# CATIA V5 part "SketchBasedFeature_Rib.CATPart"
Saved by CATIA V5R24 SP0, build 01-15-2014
Part number: Part1
Bounding box of the stored display mesh (mm): x -138.345 to 158.897, y -708.244 to 25, z -53.996 to 200
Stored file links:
  E:\Desktop_RNH\학부 CAD 수업 자료\[CAD_V2]강의자료(CAD)_2017년 이후\툴바예제\2 PartDesign\Upload2_1_modified\SketchBasedFeature_Rib.CATPart

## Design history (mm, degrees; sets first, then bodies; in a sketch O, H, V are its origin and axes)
Set1
  Plane1: type Offset, RefPlane zx-plane, Offset 25
  Plane2: type Offset, RefPlane zx-plane, Offset 25, reversed
  Sketch1 on Plane1, origin (0, 25, 0), H (-1, 0, 0), V (0, 0, 1)
    line L1 (0, 0) -> (30, 0)
    arc A1 centre (30, -70) radius 70 from (30, 0) to (79.8659, -20.8737) cw
    line L2 (79.8659, -20.8737) -> (112.4973, -53.9964)
    horizontal: L1 H
    tangency: A1 L1, A1 L2
  Sketch2 on Plane2, origin (0, -25, 0), H (-1, 0, 0), V (0, 0, 1)
    line L1 (0, 0) -> (91.7373, 0)
    arc A1 centre (91.7373, -25.9663) radius 25.9663 from (91.7373, 0) to (112.2979, -10.1072) cw
    line L2 (112.2979, -10.1072) -> (136.3218, -41.2531)
    horizontal: L1 H
    tangency: A1 L1, L2 A1
  Loft1: Sections (Sketch2; Sketch4; Sketch1)
  Helix1: Direction {line type PtDir, RefPoint {point type OnPlane, Support xy-plane, H 10.277, V -385.624, Direction (1, 0, 0)}, Direction (0, 0, 1), Start -75, End 74}, RefPoint {point type OnPlane, Support xy-plane, H -16.418, V -239.419, Direction (1, 0, 0)}, Pitch 20, Height 200, TaperAngle 0
  Plane3: type Normal, Curve Helix1, RefPoint vertex of Helix1
  Point1: type OnPlane, Support xy-plane, H -0.103, V -708.244, Direction (1, 0, 0)
  Plane4: type Normal, Curve Helix1, RefPoint vertex of Helix1
  Sketch3 on Plane4, origin (-111.3508, -39.098, 2.5276), H (0.3313, -0.9435, 0), V (0.0202, 0.0071, 0.9998)
    circle A1 centre (216.484, 0) radius 6.9758
    point P1 (216.484, 0)
    coincidence: P1 H
Body1 "PartBody" (main body)
  Sketch4 on zx-plane, origin (0, 0, 0), H (-1, 0, 0), V (0, 0, 1)
    line L1 (0, 0) -> (62.8887, 0)
    line L2 (118.8354, -31.3961) -> (130.2791, -50.1441)
    arc A1 centre (62.8887, -65.5455) radius 65.5455 from (62.8887, 0) to (118.8354, -31.3961) cw
    horizontal: L1 H
    tangency: A1 L1, A1 L2
  Sketch5 on yz-plane, origin (0, 0, 0), H (0, 1, 0), V (0, 0, 1)
    line L1 (0, 0.3739) -> (12.6988, 0.3739)
    line L2 (12.6988, 0.3739) -> (12.6988, 10.3739)
    line L3 (12.6988, 10.3739) -> (0, 10.3739)
    line L4 (0, 10.3739) -> (0, 0.3739)
    horizontal: L1 H, L3 H
    vertical: L2 V, L4 V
